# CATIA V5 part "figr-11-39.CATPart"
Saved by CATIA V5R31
Part number: Part1
Bounding box of the stored display mesh (mm): x -177 to 59, y -180 to 60, z 0 to 80
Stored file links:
  D:\PROJECTS\Project 2021\US EDITION\CATIA V5 6R 2021\Resources\Part Files\c11_catia_v5_6r2021_prt\figr-11-39.CATPart
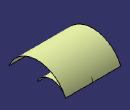
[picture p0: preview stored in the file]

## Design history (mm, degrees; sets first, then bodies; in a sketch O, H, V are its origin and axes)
Set1
  Extrude1: Element1 Sketch1, Lim1 59, Lim2 59, Direction yz-plane
  Scaling1: ToTransfor Extrude1, Reference vertex [face of Extrude1], Ratio 2
Body1 (main body)
  Sketch1 on yz-plane, origin (0, 0, 0), H (0, 1, 0), V (0, 0, 1)
    arc A1 centre (0, -25) radius 65 from (-60, 0) to (60, 0) cw
    point P2 (-60, 0)
    point P3 (60, 0)
    coincidence: P2 H, P3 H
